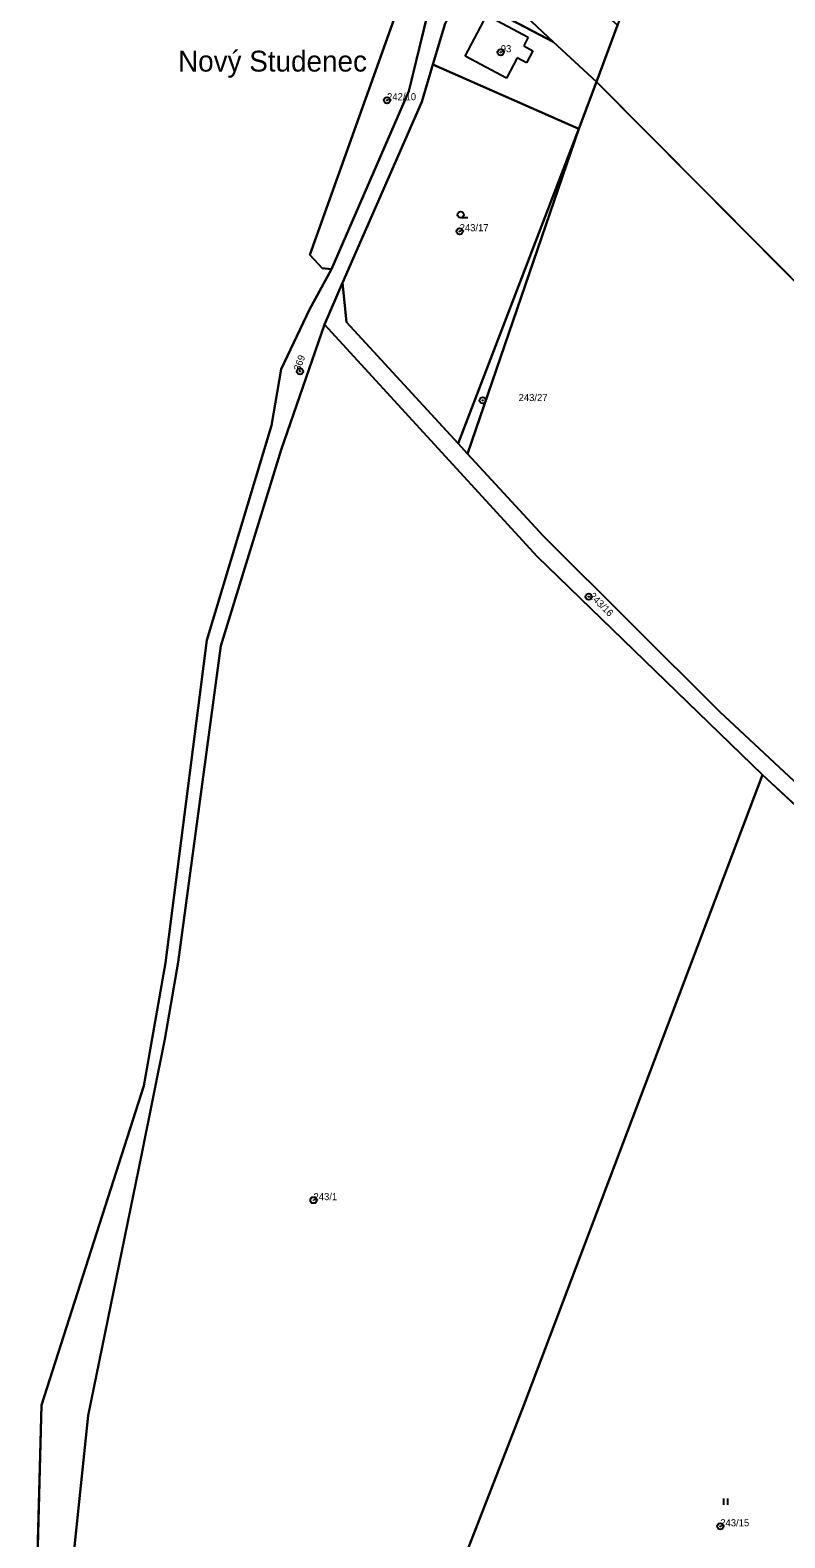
# Model space of a CAD drawing. Extents: x -652854 to -650068, y -1097661 to -1095417.
# Drawn here: x -651000.7 to -650819.6, y -1096498.9 to -1096137.1 of the extents above; entities that cross this region are included whole.
import ezdxf

# ---------------------------------------------------------------- set-up
doc = ezdxf.new("R2010")
doc.units = 0
for name, color, linetype in [('Definiční body parcel', 7, 'Continuous'), ('Hranice - vnitř_ kresba', 7, 'Continuous'), ('Hranice parcel', 7, 'Continuous'), ('Názvy', 7, 'Continuous'), ('Obvody jako plochy', 7, 'Continuous'), ('Parcelní čísla', 7, 'Continuous'), ('Prvky pro prodl_ par_ č_', 7, 'Continuous'), ('Značky kultur', 7, 'Continuous')]:
    doc.layers.add(name, color=color, linetype=linetype)

msp = doc.modelspace()

# ---------------------------------------------------------------- linework, layer by layer
at = {"layer": 'Definiční body parcel'}
for centre, radius in [((-650887.77, -1096142.37), 0.75), ((-650887.77, -1096142.37), 0.0327), ((-650915.05, -1096153.89), 0.75), ((-650915.05, -1096153.89), 0.0327), ((-650897.64, -1096185.32), 0.75), ((-650897.64, -1096185.32), 0.0327), ((-650935.96, -1096218.96), 0.75), ((-650935.96, -1096218.96), 0.0327), ((-650892.1, -1096225.92), 0.75), ((-650892.1, -1096225.92), 0.0327), ((-650866.67, -1096273.02), 0.75), ((-650866.67, -1096273.02), 0.0327), ((-650932.71, -1096417.85), 0.75), ((-650932.71, -1096417.85), 0.0327), ((-650835.09, -1096496.12), 0.75), ((-650835.09, -1096496.12), 0.0327)]:
    msp.add_circle(centre, radius, dxfattribs=at)
at = {"layer": 'Hranice - vnitř_ kresba'}
for p, q in [((-650896.34, -1096143.33), (-650891.1, -1096133.49)), ((-650891.1, -1096133.49), (-650881.17, -1096138.78)), ((-650881.17, -1096138.78), (-650882.25, -1096140.82)), ((-650882.25, -1096140.82), (-650880.04, -1096142)), ((-650880.04, -1096142), (-650881.6, -1096144.92)), ((-650886.41, -1096148.62), (-650896.34, -1096143.33)), ((-650883.81, -1096143.74), (-650886.41, -1096148.62)), ((-650881.6, -1096144.92), (-650883.81, -1096143.74))]:
    msp.add_line(p, q, dxfattribs=at)
at = {"layer": 'Hranice parcel'}
for p, q in [((-650909.81, -1096151.69), (-650902.03, -1096119.57)), ((-650894.61, -1096121.58), (-650875.22, -1096139.85)), ((-650875.22, -1096139.85), (-650897.64, -1096128.03)), ((-650913.45, -1096134.6), (-650933.62, -1096190.95)), ((-650901.13, -1096135.45), (-650904.08, -1096145.3)), ((-650859.75, -1096135.85), (-650864.8, -1096149.44)), ((-650875.22, -1096139.85), (-650864.8, -1096149.44)), ((-650904.08, -1096145.3), (-650906.68, -1096154.27)), ((-650904.08, -1096145.3), (-650869.04, -1096160.72)), ((-650869.04, -1096160.72), (-650864.8, -1096149.44)), ((-650773.22, -1096241.73), (-650864.8, -1096149.44)), ((-650928.4, -1096194.46), (-650909.81, -1096151.69)), ((-650906.68, -1096154.27), (-650925.77, -1096197.7)), ((-650869.04, -1096160.72), (-650898.03, -1096236.26)), ((-650869.04, -1096160.72), (-650895.79, -1096238.76)), ((-650933.62, -1096190.95), (-650930.6, -1096194.21)), ((-650933.65, -1096204.11), (-650928.4, -1096194.46)), ((-650930.6, -1096194.21), (-650928.4, -1096194.46)), ((-650925.77, -1096197.7), (-650930.11, -1096207.71)), ((-650924.83, -1096207.12), (-650925.77, -1096197.7)), ((-650940.47, -1096218.42), (-650933.65, -1096204.11)), ((-650930.11, -1096207.71), (-650940.46, -1096237.81)), ((-650879, -1096263.35), (-650930.11, -1096207.71)), ((-650898.03, -1096236.26), (-650924.83, -1096207.12)), ((-650942.82, -1096231.9), (-650940.47, -1096218.42)), ((-650958.28, -1096283.44), (-650942.82, -1096231.9)), ((-650895.79, -1096238.76), (-650898.03, -1096236.26)), ((-650940.46, -1096237.81), (-650954.92, -1096284.8)), ((-650877.55, -1096258.47), (-650895.79, -1096238.76)), ((-650835.17, -1096300.67), (-650877.55, -1096258.47)), ((-650824.93, -1096315.79), (-650879, -1096263.35)), ((-650968.25, -1096360.9), (-650958.28, -1096283.44)), ((-650954.92, -1096284.8), (-650965.16, -1096360.72)), ((-650804.31, -1096329.49), (-650835.17, -1096300.67)), ((-650882.2, -1096467.08), (-650824.93, -1096315.79)), ((-650771.95, -1096365.02), (-650824.93, -1096315.79)), ((-650973.44, -1096390.4), (-650968.25, -1096360.9)), ((-650965.16, -1096360.72), (-650968.42, -1096379.18)), ((-650968.42, -1096379.18), (-650973.96, -1096407.04)), ((-650997.98, -1096467.04), (-650973.44, -1096390.4)), ((-650973.96, -1096407.04), (-650986.75, -1096469.56)), ((-650997.98, -1096467.04), (-651000.71, -1096567.63)), ((-650940.33, -1096616.41), (-650882.2, -1096467.08)), ((-650986.75, -1096469.56), (-650996.98, -1096566.77))]:
    msp.add_line(p, q, dxfattribs=at)
at = {"layer": 'Obvody jako plochy'}
for points in [[(-650913.45, -1096134.6), (-650933.62, -1096190.95), (-650930.6, -1096194.21), (-650928.4, -1096194.46), (-650909.81, -1096151.69), (-650902.03, -1096119.57), (-650884.57, -1096069.52), (-650886.78, -1096073.4), (-650890.57, -1096083.1), (-650900.33, -1096105.01), (-650913.85, -1096098.99), (-650902.95, -1096107.33)], [(-650683.93, -1096329.93), (-650684.92, -1096267.36), (-650682.55, -1096225.39), (-650668.72, -1096197.09), (-650711.09, -1096192.09), (-650728.33, -1096188.58), (-650742.01, -1096181.85), (-650751.15, -1096173.61), (-650769.16, -1096151.85), (-650788.5, -1096124.42), (-650836.01, -1096073.17), (-650848.76, -1096104.66), (-650859.75, -1096135.85), (-650864.8, -1096149.44), (-650773.22, -1096241.73)], [(-650894.61, -1096121.58), (-650875.22, -1096139.85), (-650864.8, -1096149.44), (-650859.75, -1096135.85), (-650870.85, -1096125.92), (-650881.24, -1096116.57), (-650890.21, -1096108.61)], [(-650897.64, -1096128.03), (-650875.22, -1096139.85), (-650894.61, -1096121.58)], [(-650901.13, -1096135.45), (-650904.08, -1096145.3), (-650869.04, -1096160.72), (-650864.8, -1096149.44), (-650875.22, -1096139.85), (-650897.64, -1096128.03)], [(-650898.03, -1096236.26), (-650869.04, -1096160.72), (-650904.08, -1096145.3), (-650906.68, -1096154.27), (-650925.77, -1096197.7), (-650924.83, -1096207.12)], [(-650683.6, -1096346.64), (-650683.93, -1096329.93), (-650773.22, -1096241.73), (-650864.8, -1096149.44), (-650869.04, -1096160.72), (-650895.79, -1096238.76), (-650877.55, -1096258.47), (-650835.17, -1096300.67), (-650804.31, -1096329.49), (-650771.2, -1096357.19), (-650742.24, -1096382.41), (-650680.01, -1096371.46)], [(-650895.79, -1096238.76), (-650869.04, -1096160.72), (-650898.03, -1096236.26)], [(-650771.2, -1096357.19), (-650804.31, -1096329.49), (-650835.17, -1096300.67), (-650877.55, -1096258.47), (-650895.79, -1096238.76), (-650898.03, -1096236.26), (-650924.83, -1096207.12), (-650925.77, -1096197.7), (-650930.11, -1096207.71), (-650879, -1096263.35), (-650824.93, -1096315.79), (-650771.95, -1096365.02)], [(-650799.85, -1096650.9), (-650801.47, -1096660.7), (-650795.97, -1096647.36), (-650807.31, -1096617.17), (-650798.99, -1096582.65), (-650793.31, -1096549.53), (-650785.54, -1096499.95), (-650773.41, -1096422.59), (-650773.25, -1096394.71), (-650771.95, -1096365.02), (-650824.93, -1096315.79), (-650882.2, -1096467.08), (-650940.33, -1096616.41), (-650895.72, -1096750.97), (-650857.12, -1096867.39), (-650851.23, -1096836.35), (-650839.76, -1096776.84), (-650837.51, -1096768.15), (-650819.95, -1096709.68), (-650802.47, -1096650.3)]]:
    msp.add_lwpolyline(points, close=True, dxfattribs=at)
for points in [[(-650902.03, -1096119.57), (-650909.81, -1096151.69), (-650928.4, -1096194.46), (-650933.65, -1096204.11), (-650940.47, -1096218.42), (-650942.82, -1096231.9), (-650958.28, -1096283.44), (-650968.25, -1096360.9), (-650973.44, -1096390.4), (-650997.98, -1096467.04), (-651000.71, -1096567.63)], [(-651000.71, -1096567.63), (-650997.98, -1096467.04), (-650973.44, -1096390.4), (-650968.25, -1096360.9), (-650958.28, -1096283.44), (-650942.82, -1096231.9), (-650940.47, -1096218.42), (-650933.65, -1096204.11), (-650928.4, -1096194.46), (-650930.6, -1096194.21), (-650933.62, -1096190.95), (-650913.45, -1096134.6)], [(-650996.98, -1096566.77), (-650986.75, -1096469.56), (-650973.96, -1096407.04), (-650968.42, -1096379.18), (-650965.16, -1096360.72), (-650954.92, -1096284.8), (-650940.46, -1096237.81), (-650930.11, -1096207.71), (-650925.77, -1096197.7), (-650906.68, -1096154.27), (-650904.08, -1096145.3), (-650901.13, -1096135.45)], [(-650940.33, -1096616.41), (-650882.2, -1096467.08), (-650824.93, -1096315.79), (-650879, -1096263.35), (-650930.11, -1096207.71), (-650940.46, -1096237.81), (-650954.92, -1096284.8), (-650965.16, -1096360.72), (-650968.42, -1096379.18), (-650973.96, -1096407.04), (-650986.75, -1096469.56), (-650996.98, -1096566.77)]]:
    msp.add_lwpolyline(points, dxfattribs=at)
at = {"layer": 'Značky kultur'}
for p, q in [((-650895.66, -1096182.11), (-650897.41, -1096182.11)), ((-650834.307, -1096489.465), (-650834.307, -1096490.965)), ((-650833.285, -1096490.965), (-650833.285, -1096489.465))]:
    msp.add_line(p, q, dxfattribs=at)
msp.add_circle((-650897.41, -1096181.36), 0.75, dxfattribs=at)

# ---------------------------------------------------------------- texts
at = {"layer": 'Názvy'}
msp.add_text('Nový Studenec', height=5, dxfattribs=at).set_placement((-650965.22, -1096147))
at = {"layer": 'Parcelní čísla'}
for s, height, p in [('93', 1.7, (-650887.77, -1096142.37)), ('242/10', 1.7, (-650915.05, -1096153.89)), ('243/17', 1.7, (-650897.64, -1096185.32)), ('243/27', 0.1, (-650892.1, -1096225.92)), ('243/1', 1.7, (-650932.71, -1096417.85)), ('243/15', 1.7, (-650835.09, -1096496.12))]:
    msp.add_text(s, height=height, dxfattribs=at).set_placement(p)
for s, rotation, p in [('369', 69.768, (-650935.96, -1096218.96)), ('243/16', 315, (-650866.67, -1096273.02))]:
    msp.add_text(s, height=1.7, rotation=rotation, dxfattribs=at).set_placement(p)
at = {"layer": 'Prvky pro prodl_ par_ č_'}
msp.add_text('243/27', height=1.7, dxfattribs=at).set_placement((-650883.49, -1096226.08))

doc.saveas('drawing.dxf')
